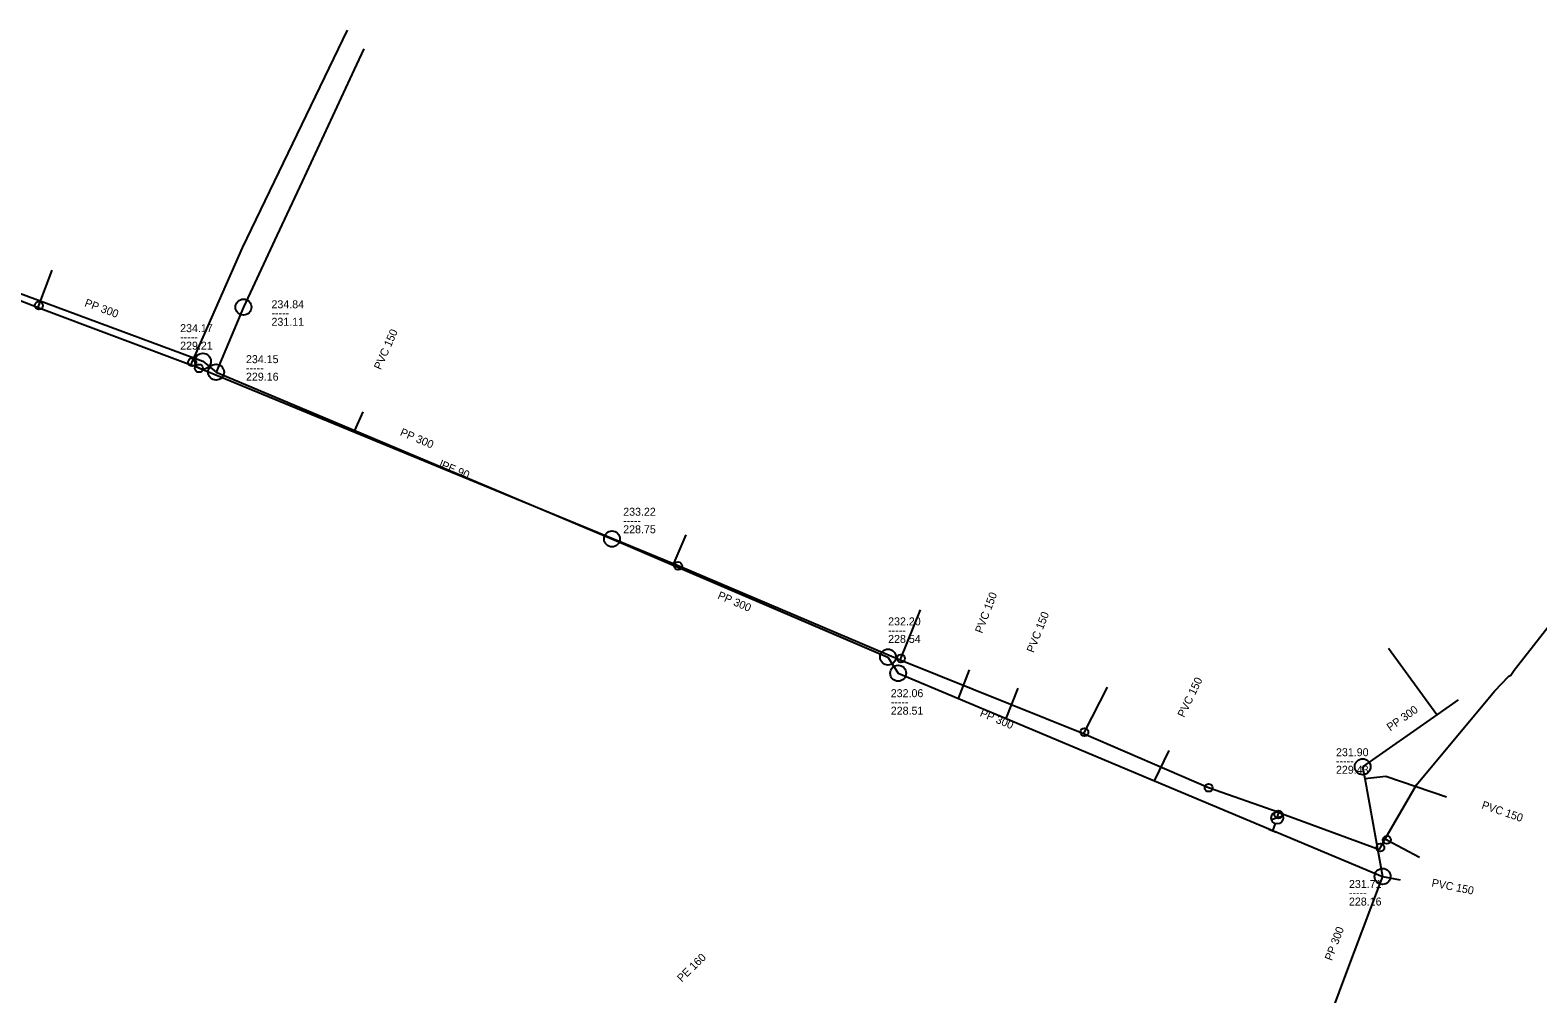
# Model space of a CAD drawing. Extents: x -771542 to -770341, y -1050442 to -1049881.
# Drawn here: x -770940.3 to -770751, y -1050239.8 to -1050118.8 of the extents above; entities that cross this region are included whole.
import ezdxf

# ---------------------------------------------------------------- set-up
doc = ezdxf.new("R2010")
doc.units = 0
doc.layers.add('Level 0', color=7, linetype='Continuous')

msp = doc.modelspace()

# ---------------------------------------------------------------- linework, layer by layer
at = {"layer": 'Level 0'}
for p, q in [((-770913.62, -1050146.14), (-770900.46, -1050118.81)), ((-770898.39, -1050121.17), (-770899.6, -1050123.76)), ((-770899.6, -1050123.76), (-770906.16, -1050137.81)), ((-770906.16, -1050137.81), (-770909.33, -1050144.6)), ((-770909.33, -1050144.6), (-770913.52, -1050153.57)), ((-770919.97, -1050160.48), (-770913.62, -1050146.14)), ((-770951.49, -1050148.19), (-770918.61, -1050160.36)), ((-770939.2, -1050153.37), (-770937.54, -1050148.94)), ((-770942.74, -1050152.26), (-770939.29, -1050153.6)), ((-770939.29, -1050153.6), (-770939.2, -1050153.37)), ((-770939.29, -1050153.6), (-770920.11, -1050160.83)), ((-770913.52, -1050153.57), (-770916.96, -1050161.73)), ((-770920.11, -1050160.83), (-770919.97, -1050160.48)), ((-770919.12, -1050161.25), (-770920.11, -1050160.83)), ((-770918.61, -1050160.36), (-770916.96, -1050161.73)), ((-770858.93, -1050186.05), (-770919.12, -1050161.25)), ((-770916.96, -1050161.73), (-770899.52, -1050169.07)), ((-770899.52, -1050169.07), (-770898.49, -1050166.73)), ((-770899.52, -1050169.07), (-770867.24, -1050182.66)), ((-770867.24, -1050182.66), (-770859.57, -1050185.94)), ((-770859.57, -1050185.94), (-770857.91, -1050182.14)), ((-770859.57, -1050185.94), (-770832.58, -1050197.49)), ((-770831.06, -1050197.89), (-770858.93, -1050186.05)), ((-770830.96, -1050197.65), (-770828.48, -1050191.55)), ((-770753.95, -1050199.13), (-770749.09, -1050192.94)), ((-770763.66, -1050204.73), (-770769.74, -1050196.43)), ((-770832.58, -1050197.49), (-770831.3, -1050199.52)), ((-770831.06, -1050197.89), (-770830.96, -1050197.65)), ((-770808.04, -1050207.14), (-770831.06, -1050197.89)), ((-770831.3, -1050199.52), (-770823.71, -1050202.7)), ((-770823.71, -1050202.7), (-770822.33, -1050199.09)), ((-770756.41, -1050201.77), (-770754.62, -1050199.88)), ((-770754.62, -1050199.88), (-770754.36, -1050199.76)), ((-770754.36, -1050199.76), (-770753.95, -1050199.13)), ((-770823.71, -1050202.7), (-770817.75, -1050205.2)), ((-770817.75, -1050205.2), (-770816.25, -1050201.41)), ((-770807.92, -1050206.91), (-770805.01, -1050201.27)), ((-770766.21, -1050213.53), (-770756.41, -1050201.77)), ((-770760.98, -1050202.85), (-770763.66, -1050204.73)), ((-770817.75, -1050205.2), (-770799.12, -1050213.01)), ((-770763.66, -1050204.73), (-770772.97, -1050211.25)), ((-770808.04, -1050207.14), (-770807.92, -1050206.91)), ((-770792.31, -1050213.88), (-770808.04, -1050207.14)), ((-770799.12, -1050213.01), (-770797.28, -1050209.2)), ((-770772.97, -1050211.25), (-770772.7, -1050212.74)), ((-770799.12, -1050213.01), (-770770.47, -1050225.02)), ((-770783.49, -1050216.99), (-770792.31, -1050213.88)), ((-770772.7, -1050212.74), (-770770.06, -1050212.42)), ((-770772.7, -1050212.74), (-770770.47, -1050225.02)), ((-770770.13, -1050220.32), (-770766.21, -1050213.53)), ((-770770.06, -1050212.42), (-770762.43, -1050215.03)), ((-770782.99, -1050217.44), (-770784.41, -1050217.9)), ((-770783.7, -1050217.67), (-770783.56, -1050217.23)), ((-770783.56, -1050217.23), (-770783.49, -1050216.99)), ((-770783.49, -1050216.99), (-770770.87, -1050221.63)), ((-770783.83, -1050219.49), (-770784.77, -1050219.14)), ((-770783.96, -1050218.37), (-770784.3, -1050219.31)), ((-770770.87, -1050221.63), (-770770.75, -1050221.4)), ((-770770.75, -1050221.4), (-770770.13, -1050220.32)), ((-770770.13, -1050220.32), (-770769.93, -1050220.43)), ((-770769.93, -1050220.43), (-770765.82, -1050222.61)), ((-770770.47, -1050225.02), (-770770.88, -1050226.1)), ((-770770.47, -1050225.02), (-770768.25, -1050225.46)), ((-770770.88, -1050226.1), (-770775.11, -1050237.31)), ((-770775.11, -1050237.31), (-770777.92, -1050244.75))]:
    msp.add_line(p, q, dxfattribs=at)
for centre, radius in [((-770939.2, -1050153.37), 0.5), ((-770913.52, -1050153.57), 1), ((-770919.97, -1050160.48), 0.5), ((-770919.12, -1050161.25), 0.5), ((-770918.61, -1050160.36), 1), ((-770916.96, -1050161.73), 1), ((-770867.24, -1050182.66), 1), ((-770858.93, -1050186.05), 0.5), ((-770832.58, -1050197.49), 1), ((-770831.3, -1050199.52), 1), ((-770830.96, -1050197.65), 0.5), ((-770807.92, -1050206.91), 0.5), ((-770772.97, -1050211.25), 1), ((-770792.31, -1050213.88), 0.5), ((-770783.7, -1050217.67), 0.75), ((-770783.56, -1050217.23), 0.5), ((-770770.75, -1050221.4), 0.5), ((-770769.93, -1050220.43), 0.5), ((-770770.47, -1050225.02), 1)]:
    msp.add_circle(centre, radius, dxfattribs=at)

# ---------------------------------------------------------------- texts
for s, rotation, p in [('PP 300', 339.684, (-770933.55, -1050153.42)), ('PVC 150', 66.242, (-770896.27, -1050161.51)), ('PP 300', 337.169, (-770893.94, -1050169.64)), ('lPE 90', 337.607, (-770889.03, -1050173.65)), ('PP 300', 336.832, (-770854.06, -1050190.11)), ('PVC 150', 69.08, (-770820.76, -1050194.58)), ('PVC 150', 68.407, (-770814.29, -1050197.02)), ('PVC 150', 64.222, (-770795.38, -1050205.15)), ('PP 300', 337.244, (-770821.12, -1050204.87)), ('PP 300', 35.049, (-770769.51, -1050206.83)), ('PVC 150', 341.116, (-770758.11, -1050216.46)), ('PVC 150', 348.789, (-770764.37, -1050226.27)), ('PP 300', 69.326, (-770776.84, -1050235.67)), ('PE 160', 44.021, (-770858.49, -1050238.34))]:
    msp.add_text(s, height=1, rotation=rotation, dxfattribs=at).set_placement(p)
for s, p in [('234.84', (-770910, -1050153.71)), ('-----', (-770910, -1050154.81)), ('231.11', (-770910, -1050155.91)), ('234.17', (-770921.47, -1050156.71)), ('-----', (-770921.47, -1050157.81)), ('229.21', (-770921.47, -1050158.91)), ('234.15', (-770913.2, -1050160.6)), ('-----', (-770913.2, -1050161.7)), ('229.16', (-770913.2, -1050162.8)), ('233.22', (-770865.83, -1050179.75)), ('-----', (-770865.83, -1050180.85)), ('228.75', (-770865.83, -1050181.95)), ('232.20', (-770832.56, -1050193.51)), ('-----', (-770832.56, -1050194.61)), ('228.54', (-770832.56, -1050195.71)), ('232.06', (-770832.23, -1050202.52)), ('-----', (-770832.23, -1050203.62)), ('228.51', (-770832.23, -1050204.72)), ('231.90', (-770776.32, -1050209.93)), ('-----', (-770776.32, -1050211.03)), ('229.43', (-770776.32, -1050212.13)), ('231.71', (-770774.69, -1050226.47)), ('-----', (-770774.69, -1050227.57)), ('228.16', (-770774.69, -1050228.67))]:
    msp.add_text(s, height=1, dxfattribs=at).set_placement(p)

doc.saveas('drawing.dxf')
